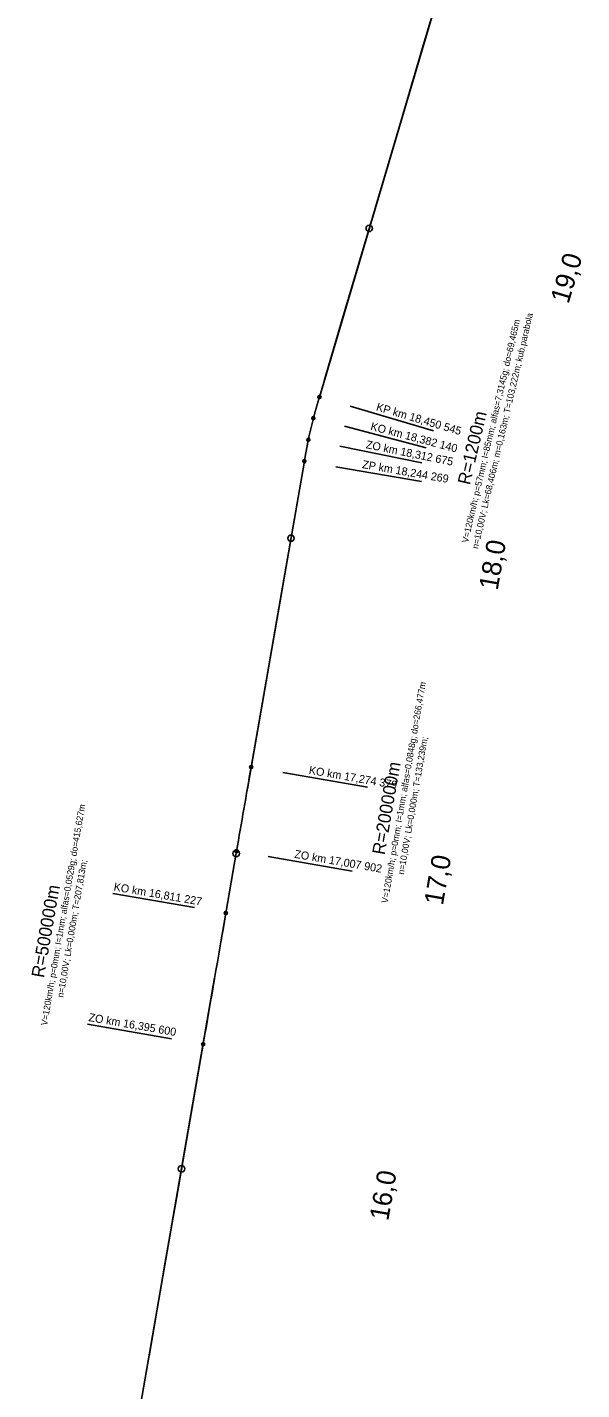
# Model space of a CAD drawing. Extents: x -504999 to -493096, y -1330712 to -1305226.
# Drawn here: x -496878 to -495146, y -1323937 to -1319679 of the extents above; entities that cross this region are included whole.
import ezdxf

# ---------------------------------------------------------------- set-up
doc = ezdxf.new("R2010")
doc.units = 0
for name, color, linetype in [('0_HM', 7, 'Continuous'), ('0_obluky', 7, 'Continuous'), ('0_popis oblukov', 7, 'Continuous'), ('0_stanicenie oblukov', 7, 'Continuous'), ('dotyčnice', 7, 'Continuous'), ('Level 1', 7, 'Continuous')]:
    doc.layers.add(name, color=color, linetype=linetype)

msp = doc.modelspace()

# ---------------------------------------------------------------- linework, layer by layer
at = {"layer": '0_HM'}
for centre in [(-495810.1, -1320307.8), (-496054.5, -1321276.1), (-496225.8, -1322261.4), (-496396.4, -1323246.7)]:
    msp.add_circle(centre, 10, dxfattribs=at)
at = {"layer": '0_obluky'}
for p, q in [((-495965.7, -1320834.8), (-495324.3, -1318662.9)), ((-496178.9, -1321991), (-496012.7, -1321035.5)), ((-496224.4, -1322253.5), (-496273.6, -1322538.4)), ((-496257.9, -1322447.4), (-496224.4, -1322253.6)), ((-496878.3, -1326024.3), (-496328.8, -1322856.9))]:
    msp.add_line(p, q, dxfattribs=at)
for points in [[(-495965.7, -1320834.8), (-495966, -1320835.8), (-495966.3, -1320836.7), (-495966.6, -1320837.7), (-495966.9, -1320838.7), (-495967.2, -1320839.6), (-495967.4, -1320840.6), (-495967.7, -1320841.5), (-495968, -1320842.5), (-495968.3, -1320843.5), (-495968.6, -1320844.4), (-495968.9, -1320845.4), (-495969.1, -1320846.4), (-495969.4, -1320847.3), (-495969.7, -1320848.3), (-495970, -1320849.3), (-495970.3, -1320850.2), (-495970.6, -1320851.2), (-495970.8, -1320852.2), (-495971.1, -1320853.1), (-495971.4, -1320854.1), (-495971.7, -1320855.1), (-495972, -1320856), (-495972.3, -1320857), (-495972.5, -1320858), (-495972.8, -1320858.9), (-495973.1, -1320859.9), (-495973.4, -1320860.9), (-495973.7, -1320861.8), (-495973.9, -1320862.8), (-495974.2, -1320863.8), (-495974.5, -1320864.7), (-495974.8, -1320865.7), (-495975.1, -1320866.7), (-495975.3, -1320867.6), (-495975.6, -1320868.6), (-495975.9, -1320869.6), (-495976.2, -1320870.5), (-495976.4, -1320871.5), (-495976.7, -1320872.5), (-495977, -1320873.4), (-495977.3, -1320874.4), (-495977.5, -1320875.4), (-495977.8, -1320876.3), (-495978.1, -1320877.3), (-495978.4, -1320878.3), (-495978.6, -1320879.2), (-495978.9, -1320880.2), (-495979.2, -1320881.2), (-495979.5, -1320882.1), (-495979.7, -1320883.1), (-495980, -1320884.1), (-495980.3, -1320885), (-495980.5, -1320886), (-495980.8, -1320887), (-495981.1, -1320888), (-495981.3, -1320888.9), (-495981.6, -1320889.9), (-495981.9, -1320890.9), (-495982.1, -1320891.8), (-495982.4, -1320892.8), (-495982.7, -1320893.8), (-495982.9, -1320894.7), (-495983.2, -1320895.7), (-495983.4, -1320896.7), (-495983.7, -1320897.7), (-495984, -1320898.6), (-495984.2, -1320899.6), (-495984.5, -1320900.6)], [(-496012.7, -1321035.5), (-496012.5, -1321034.5), (-496012.3, -1321033.5), (-496012.1, -1321032.5), (-496012, -1321031.5), (-496011.8, -1321030.5), (-496011.6, -1321029.5), (-496011.5, -1321028.5), (-496011.3, -1321027.6), (-496011.1, -1321026.6), (-496010.9, -1321025.6), (-496010.8, -1321024.6), (-496010.6, -1321023.6), (-496010.4, -1321022.6), (-496010.2, -1321021.6), (-496010.1, -1321020.6), (-496009.9, -1321019.6), (-496009.7, -1321018.6), (-496009.5, -1321017.7), (-496009.4, -1321016.7), (-496009.2, -1321015.7), (-496009, -1321014.7), (-496008.8, -1321013.7), (-496008.7, -1321012.7), (-496008.5, -1321011.7), (-496008.3, -1321010.7), (-496008.1, -1321009.7), (-496008, -1321008.7), (-496007.8, -1321007.7), (-496007.6, -1321006.8), (-496007.4, -1321005.8), (-496007.3, -1321004.8), (-496007.1, -1321003.8), (-496006.9, -1321002.8), (-496006.7, -1321001.8), (-496006.5, -1321000.8), (-496006.4, -1320999.8), (-496006.2, -1320998.8), (-496006, -1320997.8), (-496005.8, -1320996.9), (-496005.6, -1320995.9), (-496005.5, -1320994.9), (-496005.3, -1320993.9), (-496005.1, -1320992.9), (-496004.9, -1320991.9), (-496004.7, -1320990.9), (-496004.5, -1320989.9), (-496004.3, -1320988.9), (-496004.2, -1320988), (-496004, -1320987), (-496003.8, -1320986), (-496003.6, -1320985), (-496003.4, -1320984), (-496003.2, -1320983), (-496003, -1320982), (-496002.8, -1320981), (-496002.6, -1320980.1), (-496002.5, -1320979.1), (-496002.3, -1320978.1), (-496002.1, -1320977.1), (-496001.9, -1320976.1), (-496001.7, -1320975.1), (-496001.5, -1320974.1), (-496001.3, -1320973.1), (-496001.1, -1320972.2), (-496000.9, -1320971.2), (-496000.7, -1320970.2), (-496000.5, -1320969.2), (-496000.3, -1320968.2)]]:
    msp.add_lwpolyline(points, dxfattribs=at)
for centre in [(-495965.7, -1320834.8), (-495984.5, -1320900.6), (-496000.3, -1320968.2), (-496012.7, -1321035.5), (-496178.9, -1321991), (-496224.4, -1322253.6), (-496257.9, -1322447.4), (-496328.8, -1322856.9)]:
    msp.add_circle(centre, 5, dxfattribs=at)
for centre, radius, start, end in [((-494824.4, -1321207.5), 1200, 165.1791, 168.4958), ((-299139.7, -1356277.1), 200000, 170.129, 170.20534), ((-988969.8, -1237388.6), 500000, 350.157712, 350.20534)]:
    msp.add_arc(centre, radius, start, end, dxfattribs=at)
at = {"layer": '0_stanicenie oblukov'}
for p, q in [((-495869.8, -1320863.1), (-495609.6, -1320940)), ((-495887.8, -1320926.2), (-495632, -1320993.8)), ((-495902.3, -1320988.2), (-495645.4, -1321040.4)), ((-495914.1, -1321052.6), (-495647.1, -1321099.1)), ((-496080.4, -1322008.2), (-495816, -1322054.2)), ((-496125.9, -1322270.6), (-495863, -1322316)), ((-496356.4, -1322430.4), (-496611.3, -1322386.4)), ((-496427.3, -1322839.8), (-496689.9, -1322794.3))]:
    msp.add_line(p, q, dxfattribs=at)
at = {"layer": 'dotyčnice'}
for p, q in [((-495950, -1320781.4), (-495319.2, -1318645.8)), ((-496190.7, -1322058.7), (-496028.2, -1321125.1)), ((-496862.1, -1325930.8), (-496292.9, -1322649.9))]:
    msp.add_line(p, q, dxfattribs=at)
at = {"layer": 'Level 1'}
for points in [[(-495319.2, -1318645.8), (-495399, -1318917.3), (-495440, -1319054.9), (-495488.6, -1319220.8), (-495529.8, -1319360.2), (-495541.6, -1319400.2), (-495607.3, -1319622.1), (-495638.3, -1319726.1), (-495723, -1320013.6), (-495808.7, -1320301.9), (-495896.2, -1320599.5), (-495950, -1320781.4)], [(-496028.2, -1321125.1), (-496100.1, -1321536), (-496156.4, -1321860.9), (-496190.7, -1322058.7)], [(-496292.9, -1322649.9), (-496344.5, -1322947), (-496412.6, -1323339.2), (-496447.2, -1323538.3), (-496497.5, -1323832)]]:
    msp.add_lwpolyline(points, dxfattribs=at)

# ---------------------------------------------------------------- texts
at = {"layer": '0_HM'}
for s, rotation, p in [('19,0', 73.546, (-495187.7, -1320545.8)), ('18,0', 80.129, (-495409, -1321440.8)), ('17,0', 80.2053, (-495580.1, -1322425.2)), ('16,0', 80.1577, (-495750.8, -1323411))]:
    msp.add_text(s, height=60, rotation=rotation, dxfattribs=at).set_placement(p)
at = {"layer": '0_popis oblukov'}
for s, height, rotation, p in [('V=120km/h; p=57mm; I=85mm; alfas=7,3145g; do=69,465m', 20, 76.8375, (-495501.8, -1321291.6)), ('n=10,00V; Lk=68,406m; m=0,163m; T=103,222m; kub.parabola', 20, 76.8375, (-495470.3, -1321310.3)), ('R=1200m', 40, 76.8375, (-495495.7, -1321111.5)), ('V=120km/h; p=0mm; I=1mm; alfas=0,0848g; do=266,477m', 20, 80.1672, (-495752.5, -1322417.4)), ('n=10,00V; Lk=0,000m; T=133,239m;', 20, 80.1672, (-495701.5, -1322328)), ('R=200000m', 40, 80.1672, (-495761.9, -1322267.1)), ('V=120km/h; p=0mm; I=1mm; alfas=0,0529g; do=415,627m', 20, 80.1815, (-496816.4, -1322799.7)), ('n=10,00V; Lk=0,000m; T=207,813m;', 20, 80.1815, (-496765.8, -1322712.3)), ('R=500000m', 40, 80.1815, (-496826.3, -1322651.4))]:
    msp.add_text(s, height=height, rotation=rotation, dxfattribs=at).set_placement(p)
at = {"layer": '0_stanicenie oblukov'}
for s, rotation, p in [('KP km 18,450 545', 343.546, (-495790.3, -1320876.2)), ('KO km 18,382 140', 345.1791, (-495807.9, -1320937)), ('ZO km 18,312 675', 348.4958, (-495821.9, -1320994.3)), ('ZP km 18,244 269', 350.129, (-495833.6, -1321056.5)), ('KO km 17,274 379', 350.129, (-495999.9, -1322012)), ('ZO km 17,007 902', 350.2053, (-496045.4, -1322274.3)), ('KO km 16,811 227', 350.2053, (-496609.6, -1322376.5)), ('ZO km 16,395 600', 350.1577, (-496688.2, -1322784.4))]:
    msp.add_text(s, height=25, rotation=rotation, dxfattribs=at).set_placement(p)

doc.saveas('drawing.dxf')
